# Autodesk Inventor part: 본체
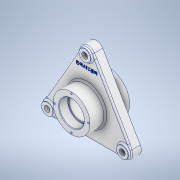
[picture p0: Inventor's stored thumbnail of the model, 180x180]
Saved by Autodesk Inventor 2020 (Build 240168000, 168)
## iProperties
Created: 2023-04
Part Number: 본체
Material: 알루미늄 6061
Document SubType Name: Modeling
Designer: 101-13
Density: 2.7 g/cm^3
Appearance: 알루미늄 - 평지
Mass: 1076.54 g
Surface Area: 609.974 cm^2
Volume: 398.717 cm^3
Author: 101-13
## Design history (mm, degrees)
sketch "스케치1" dims "d0" = 164
  geometry: L1 (0, 89.768)-(0, -89.768); L2 (-111.881, 0)-(111.881, 0); L3 (55.941, -96.892)-(-55.941, 96.892); L4 (55.941, 96.892)-(-55.941, -96.892); L5 (-83.138, -34)-(-12.124, 89); L6 (13.636, 86.382)-(83.138, -34); L7 (-71.014, -55)-(71.014, -55); L8 (13.636, 86.382)-(12.124, 89); C1 r 11 at (0, 82); C2 r 11 at (-71.014, -41); C3 r 11 at (71.014, -41); A1 r 14 centre (71.014, -41) between (71.014, -55) and (83.138, -34); A2 r 14 centre (0, 82) between (12.124, 89) and (-12.124, 89); A3 r 14 centre (-71.014, -41) between (-83.138, -34) and (-71.014, -55); 6 further points
  constraints: 16 end point, 6 centre point, 6 point on circle, 3 coincident, 2 midpoint, 2 point on line, 1 horizontal, 1 tangent, 1 vertical, 1 vertical alignment, 21 other
  dimensions: "d1" = 22 diameter of C1; "d4" = 360 deg dimension on point (0, 0) L2.start (derived)
extrude "돌출1" new body sketch "스케치1" stored distance "d12" = 18; taper "d13" = 0 deg
extrude "돌출3" join sketch "스케치1" distance "d16" = 13; taper "d17" = 0 deg
sketch "스케치5"
  geometry: C1 r 35 at (0, 0); 1 further point
  constraints: 1 centre point, 1 coincident
  dimensions: "d19" = 70 diameter of C1
extrude "돌출4" join sketch "스케치5" distance "d20" = 29; taper "d21" = 0 deg
sketch "스케치6"
  geometry: C1 r 45 at (0, 0); 1 further point
  constraints: 1 centre point, 1 coincident
  dimensions: "d22" = 90 diameter of C1
extrude "돌출5" join sketch "스케치6" distance "d23" = 5; taper "d24" = 0 deg
sketch "스케치7"
  geometry: C1 r 40 at (0, 0); 1 further point
  constraints: 1 centre point, 1 coincident
  dimensions: "d25" = 80 diameter of C1
extrude "돌출6" join sketch "스케치7" distance "d26" = 18; taper "d27" = 0 deg
fillet "모깎기1" dims "d28" = 3
fillet "모깎기2" dims "d29" = 3
fillet "모깎기3" dims "d30" = 3
fillet "모깎기4" dims "d31" = 3
sketch "스케치8"
  geometry: 2 further points
hole "구멍1" sketch "스케치8" at (0, 0) diameter "d32" = 11; stored, may be unused: countersink angle "d36" = 90 deg, drill point angle "d38" = 118 deg; dims "d33" = 8, "d34" = 4, "d35" = 2, "d37" = 10
sketch "스케치9"
  geometry: 1 further point
hole "구멍2" sketch "스케치9" at (0, 0) diameter "d42" = 42; stored, may be unused: countersink angle "d46" = 82 deg, drill point angle "d48" = 118 deg; dims "d43" = 8, "d44" = 3.023, "d45" = 2, "d47" = 10
sketch "스케치10"
  geometry: 1 further point
hole "구멍3" sketch "스케치10" at (0, 0) diameter "d49" = 47; stored, may be unused: countersink angle "d53" = 82 deg, drill point angle "d55" = 0 deg; dims "d50" = 8, "d51" = 3.023, "d52" = 2, "d54" = 17
sketch "스케치11"
  geometry: 1 further point
hole "구멍4" sketch "스케치11" at (0, 0) diameter "d56" = 47; stored, may be unused: countersink angle "d60" = 82 deg, drill point angle "d62" = 0 deg; dims "d57" = 8, "d58" = 3.023, "d59" = 2, "d61" = 17
sketch "스케치12" dims "d63" = 64
  geometry: 3 further points
  constraints: 1 coincident, 1 vertical alignment, 2 other
hole "구멍5" sketch "스케치12" at (0, 32) diameter "d64" = 3.242; stored, may be unused: countersink angle "d68" = 82 deg, drill point angle "d70" = 118 deg; dims "d65" = 8, "d66" = 3.023, "d67" = 2, "d69" = 10
sketch "스케치13" dims "d74" = 64
  geometry: 3 further points
  constraints: 1 coincident, 1 vertical alignment, 2 other
hole "구멍6" sketch "스케치13" at (0, 32) diameter "d75" = 3.242; stored, may be unused: countersink angle "d79" = 82 deg, drill point angle "d81" = 118 deg; dims "d76" = 8, "d77" = 3.023, "d78" = 2, "d80" = 10
chamfer "모따기1" distance "d85" = 1; stored, may be unused: second distance "d86" = 2, angle "d87" = 45 deg
fillet "모깎기5" dims "d88" = 0.6
fillet "모깎기6" dims "d89" = 0.6
sketch "스케치14"
  geometry: 2 further points
  constraints: 1 vertical alignment, 1 other
  dimensions: "d90" = 60 distance of point (0, 60) point (0, 0)
feature "엠보싱1" sketch "스케치14" dims "d0" = 164, "d1" = 22, "d4" = 360 deg (derived), "d16" = 13, "d91" = 0.5, "d92" = 0
node "솔리드1"
pattern_circular "원형 패턴1" dims angle "d40" = 360 deg
pattern_circular "원형 패턴2" dims angle "d72" = 360 deg
pattern_circular "원형 패턴3" dims angle "d83" = 360 deg
feature "A9D066F2-1C7D-4E18-AEED-F7BC21143FA4" dims "d32" = 11, "d33" = 8, "d34" = 4, "d35" = 2, "d36" = 90 deg, "d37" = 10, "d38" = 118 deg
other parameters: "d6" = 3, "d7" = 3, "d8" = 3, "d9" = 3, "d10" = 3, "d11" = 3
